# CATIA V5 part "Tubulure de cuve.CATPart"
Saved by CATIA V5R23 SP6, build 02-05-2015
Part number: Tubulure de cuve
Publications: "CATRouHole1", "CATRouCenter1", "CATRouCircular1", "CATRouDatumPt1"
Bounding box of the stored display mesh (mm): x -499.988 to 499.994, y -500 to 600, z 2.793 to 973
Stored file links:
  \\etu.ad.univ-lorraine.fr\bordron1\Documents\Parts EPR\Tubulure de cuve.CATPart
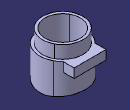
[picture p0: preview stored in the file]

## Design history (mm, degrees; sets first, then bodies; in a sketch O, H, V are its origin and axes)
AxisSystem1: origin (0, 0, 0), X (1, 0, 0), Y (0, 1, 0), Z (0, 0, 1)
Set1
  Plane1: type Offset, RefPlane ZX plane of AxisSystem1, Offset 600
  Point1: type Center, Curve edge [face of Shaft1 from Sketch1.L3 | face of Shaft1 from Sketch1.L2]
Body1 (main body)
  Sketch1 on ZX plane of AxisSystem1, origin (0, 0, 0), H (0, 0, 1), V (1, 0, 0)
    line L1 (0, -500) -> (693, -500)
    point P1 (0, -500)
    line L2 (0, -385) -> (973, -385)
    point P3 (0, -385)
    line L3 (973, -385) -> (973, -442.5)
    line L4 (973, -442.5) -> (693, -442.5)
    line L5 (693, -442.5) -> (693, -500)
    reference projected line E1 through (0, 0) direction (1, 0) from edge [ZX plane of AxisSystem1 | YZ plane of AxisSystem1]
    reference projected line E2 through (0, 0) direction (1, 0) from edge [ZX plane of AxisSystem1 | YZ plane of AxisSystem1]
    line L6 (0, -385) -> (0, -500)
    distance E1 L2 = 385
    length L2 = 973
    length L4 = 280
    distance L1 E2 = 500
    coincidence: P1 V, P3 V
    horizontal: L1 H, L2 H, L4 H
    vertical: L3 V, L5 V, L6 V
    symmetry: L1 L2 L4
  Shaft1: profile Sketch1, axis edge [ZX plane of AxisSystem1 | YZ plane of AxisSystem1], angle 360
  Sketch2 on Plane1, origin (0, 600, 0), H (0, 0, 1), V (1, 0, 0)
    line L1 (493, 350) -> (693, 350)
    line L2 (693, 350) -> (693, -350)
    line L3 (693, -350) -> (493, -350)
    line L4 (493, -350) -> (493, 350)
    reference intersected line E1 through (0, 0) direction (-1, 0) from YZ plane of AxisSystem1
    reference projected line E2 (693, 500) -> (693, -500) from edge [face of Shaft1 from Sketch1.L1 | face of Shaft1 from Sketch1.L5]
    length L3 = 200
    distance L3 L1 = 700
    horizontal: L1 H, L3 H
    vertical: L2 V, L4 V
    symmetry: L3 L1 E1
    coincidence: L2 E2
  Pad1: profile Sketch2, direction (0, 1, 0), up to the existing solid (limit type 2)
  Sketch3 on ZX plane of AxisSystem1, origin (0, 0, 0), H (0, 0, 1), V (1, 0, 0)
    circle A1 centre (-2078, 0) radius 2140
    point P1 (-2078, 0)
    radius A1 = 2140
    distance A1 V = 62
    coincidence: P1 H
  Pocket1: profile Sketch3, direction (0, -1, 0), length 550, mirrored extent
